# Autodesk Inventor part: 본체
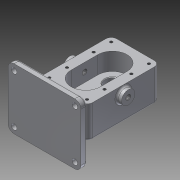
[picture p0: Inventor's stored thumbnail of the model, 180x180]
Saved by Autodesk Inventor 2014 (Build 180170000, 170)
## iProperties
Created: 2020-04
Part Number: 본체
Material: 알루미늄 6061
Document SubType Name: Modeling
Designer: kh
Density: 2.71 g/cm^3
Appearance: 알루미늄 - 평지
Mass: 1477.4 g
Surface Area: 819.403 cm^2
Volume: 545.165 cm^3
Author: kh
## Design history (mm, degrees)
sketch "스케치1"
  geometry: L1 (-40, -60)-(40, -60); L2 (40, -60)-(40, 60); L3 (40, 60)-(-40, 60); L4 (-40, 60)-(-40, -60); L5 (-40, -60)-(40, 60); L6 (40, -60)-(-40, 60); 1 further point
  constraints: 12 end point, 2 midpoint, 2 parallel, 1 horizontal, 1 perpendicular
  dimensions: "d0" = 80 distance of L3.end L2.end; "d1" = 120 distance of L2.end L1.end
extrude "돌출1" new body sketch "스케치1" distance "d2" = 53; taper "d3" = 0 deg
fillet "모깎기1" dims "d4" = 9
sketch "스케치2"
  geometry: L1 (0, 22)-(0, -22); L2 (-24, 22)-(-24, -22); L3 (24, -22)-(24, 22); A1 r 24 centre (0, 22) between (24, 22) and (-24, 22); A2 r 24 centre (0, -22) between (-24, -22) and (24, -22); 2 further points
  constraints: 8 end point, 4 point on circle, 4 tangent, 2 centre point, 2 coincident, 1 midpoint, 1 parallel, 1 vertical
  dimensions: "d5" = 44 distance of L1.start L1.end; "d6" = 48 diameter of A2
extrude "돌출2" cut sketch "스케치2" distance "d7" = 29; taper "d8" = 0 deg
sketch "스케치3"
  geometry: 3 further points
  constraints: 2 vertical alignment
  dimensions: "d9" = 22 distance of point (0, 0) point (0, 22); "d10" = 22 distance of point (0, 0) point (0, -22)
hole "구멍1" sketch "스케치3" at (0, 22), (0, -22) diameter "d11" = 25; stored, may be unused: countersink angle "d15" = 90 deg, drill point angle "d17" = 0 deg; dims "d12" = 6, "d13" = 4, "d14" = 2, "d16" = 15
sketch "스케치4"
  geometry: C1 r 12.5 at (0, 22) reference; C2 r 19 at (0, 22); 1 further point
  constraints: 1 centre point, 1 coincident
  dimensions: "d18" = 38 diameter of C2
extrude "돌출3" join sketch "스케치4" distance "d19" = 17; taper "d20" = 0 deg
hole "구멍2" diameter "d23" = 28; stored, may be unused: countersink angle "d27" = 90 deg, drill point angle "d29" = 0 deg; dims "d21" = 10, "d22" = 10, "d24" = 6, "d25" = 4, "d26" = 2, "d28" = 7.3
hole "구멍3" diameter "d32" = 17; stored, may be unused: countersink angle "d36" = 90 deg, drill point angle "d38" = 0 deg; dims "d30" = 10, "d31" = 10, "d33" = 6, "d34" = 4, "d35" = 2, "d37" = 7.3
chamfer "모따기1" distance "d39" = 0.7; stored, may be unused: second distance "d40" = 2, angle "d41" = 30 deg
fillet "모깎기2" dims "d42" = 0.5
chamfer "모따기2" distance "d43" = 1; stored, may be unused: second distance "d44" = 2, angle "d45" = 30 deg
sketch "스케치5"
  geometry: 9 further points
  constraints: 6 vertical alignment, 4 horizontal alignment
  dimensions: "d46" = 22 vertical distance of point (31, 22) point (0, 0); "d47" = 44 distance of point (31, 22) point (31, -22); "d48" = 29 distance of point (31, 51) point (31, 22); "d49" = 102 distance of point (31, -51) point (31, 51); "d50" = 62 distance of point (31, 51) point (-31, 51); "d51" = 31 horizontal distance of point (0, 0) point (31, -51)
hole "구멍4" sketch "스케치5" at (-31, 51), (31, 51), (31, 22), (31, -22), (31, -51), (-31, -51), (-31, -22), (-31, 22) diameter "d52" = 4.459; stored, may be unused: countersink angle "d56" = 90 deg, drill point angle "d58" = 118 deg; dims "d53" = 10, "d54" = 4, "d55" = 2, "d57" = 12
node "작업 평면1"
sketch "스케치6"
  geometry: L1 (-60, -70)-(60, -70); L2 (60, -70)-(60, 30); L3 (60, 30)-(-60, 30); L4 (-60, 30)-(-60, -70); L5 (-60, -70)-(60, 30); L6 (60, -70)-(-60, 30); L7 (-19, -70)-(19, -70) reference; 3 further points
  constraints: 12 end point, 4 midpoint, 2 parallel, 1 horizontal, 1 perpendicular
  dimensions: "d60" = 120 distance of L3.end L2.end; "d61" = 100 distance of L2.end L1.end
extrude "돌출4" join sketch "스케치6" distance "d62" = 10; taper "d63" = 0 deg
fillet "모깎기3" dims "d64" = 10
sketch "스케치7"
  geometry: L1 (-50, -30)-(50, -30) reference; L2 (60, -20)-(60, 60) reference; 5 further points
  constraints: 2 horizontal alignment, 2 vertical alignment
  dimensions: "d65" = 100 distance of point (50, 60) point (-50, 60); "d66" = 80 distance of point (50, 60) point (50, -20); "d67" = 10 distance from line of L1 point (50, -20); "d68" = 10 distance from line of L2 point (50, -20)
hole "구멍5" sketch "스케치7" at (-50, 60), (-50, -20), (50, -20), (50, 60) diameter "d69" = 9; stored, may be unused: countersink angle "d73" = 90 deg, drill point angle "d75" = 0 deg; dims "d70" = 9, "d71" = 4, "d72" = 2, "d74" = 12
fillet "모깎기4" dims "d76" = 3
sketch "스케치8"
  geometry: L1 (24, 16.5)-(-24, 16.5); L2 (-24, 16.5)-(-24, 36.5); L3 (-24, 36.5)-(24, 36.5); L4 (24, 36.5)-(24, 16.5); L5 (24, 16.5)-(-24, 36.5); L6 (-24, 16.5)-(24, 36.5); L7 (31, 53)-(31, 0) reference; L8 (-31, 53)-(31, 53) reference; L9 (-31, 0)-(-31, 53) reference; L10 (31, 0)-(-31, 0) reference; 6 further points
  constraints: 12 end point, 6 midpoint, 2 parallel, 1 horizontal, 1 horizontal alignment, 1 perpendicular, 1 vertical alignment
  dimensions: "d77" = 48 distance of L2.end L3.end; "d78" = 20 distance of L1.end L2.end
extrude "돌출5" join sketch "스케치8" stored distance "d79" = 10; taper "d80" = 0 deg
sketch "스케치9"
  geometry: L1 (-80, 20)-(-80, -60) reference; L2 (-80, -53)-(-67.182, -45.6); L3 (-80, -53)-(-65.199, -53); L4 (-83, -70)-(-90, -70) reference; 1 further point
  constraints: 4 end point, 1 equal length, 1 horizontal, 1 point on line
  dimensions: "d81" = 30 deg angle of L3 L2; "d82" = 17 distance from line of L4 L2.start
feature "리브1" sketch "스케치9" dims "d83" = 1, "d84" = 48, "d85" = 0, "d86" = 0, "d87" = 1, "d88" = 1
sketch "스케치10"
  geometry: L1 (-80, 20)-(-80, -60) reference; L2 (-80, 0)-(-66.947, -7.536); L3 (-80, 0)-(-64.928, 0); L4 (-80, -53)-(-60, -41.453) reference; 1 further point
  constraints: 4 end point, 1 equal length, 1 horizontal, 1 point on line
  dimensions: "d89" = 30 deg angle of L2 L3; "d90" = 53 distance of L2.start L4.start
feature "리브2" sketch "스케치10" dims "d91" = 1, "d92" = 48, "d93" = 0, "d94" = 0, "d95" = 1, "d96" = 1
sketch "스케치11"
  geometry: L1 (-20.739, -16.998)-(20.739, -16.998); L2 (20.739, -16.998)-(20.739, -23.002); L3 (20.739, -23.002)-(-20.739, -23.002); L4 (-20.739, -23.002)-(-20.739, -16.998); L5 (-20.739, -16.998)-(20.739, -23.002); L6 (20.739, -16.998)-(-20.739, -23.002); L7 (-50, -30)-(50, -30) reference; L8 (-60, 60)-(-60, -20) reference; 2 further points
  constraints: 4 end point, 1 midpoint, 2 other
  dimensions: "d97" = 10 distance from line of L7 point (0, -20); "d98" = 60 distance from line of point (0, -20) L8
feature "엠보싱1" sketch "스케치11" dims "d0" = 80, "d1" = 120, "d99" = 0.5, "d100" = 0
sketch "스케치12"
  geometry: L1 (-20, -39)-(60, -39) reference; C1 r 11 at (14, 51); 2 further points
  constraints: 1 centre point, 1 coincident
  dimensions: "d101" = 14 distance of point (14, 51) point (0, 51); "d102" = 90 distance from line of L1 point (14, 51); "d103" = 22 diameter of C1
extrude "돌출6" join sketch "스케치12" distance "d104" = 8; taper "d105" = 0 deg
sketch "스케치13"
  geometry: C1 r 11 at (-14, 51) reference; C2 r 11 at (-14, 51); 1 further point
  constraints: 1 centre point, 1 coincident
  dimensions: "d106" = 22 diameter of C2
extrude "돌출7" join sketch "스케치13" distance "d107" = 8; taper "d108" = 0 deg
hole "구멍6" diameter "d111" = 8.376; stored, may be unused: countersink angle "d115" = 90 deg, drill point angle "d117" = 0 deg; dims "d109" = 10, "d110" = 10, "d112" = 9, "d113" = 4, "d114" = 2, "d116" = 12
fillet "모깎기5" dims "d118" = 3
fillet "모깎기6" dims "d119" = 3
fillet "모깎기7" dims "d120" = 3
fillet "모깎기8" dims "d121" = 3
fillet "모깎기9" dims "d122" = 3
node "솔리드1"
node "투영된 루프1"
